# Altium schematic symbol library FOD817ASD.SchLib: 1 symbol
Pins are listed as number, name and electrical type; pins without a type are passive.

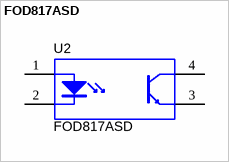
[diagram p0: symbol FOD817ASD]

## FOD817ASD
designator U2
IC, Optocoupler, 5000V, 80-160% CTR; Manufacturer: Fairchild Semiconductor; U/M: EA
footprint N04C
pins: 1 A, 2 K, 3 E, 4 C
